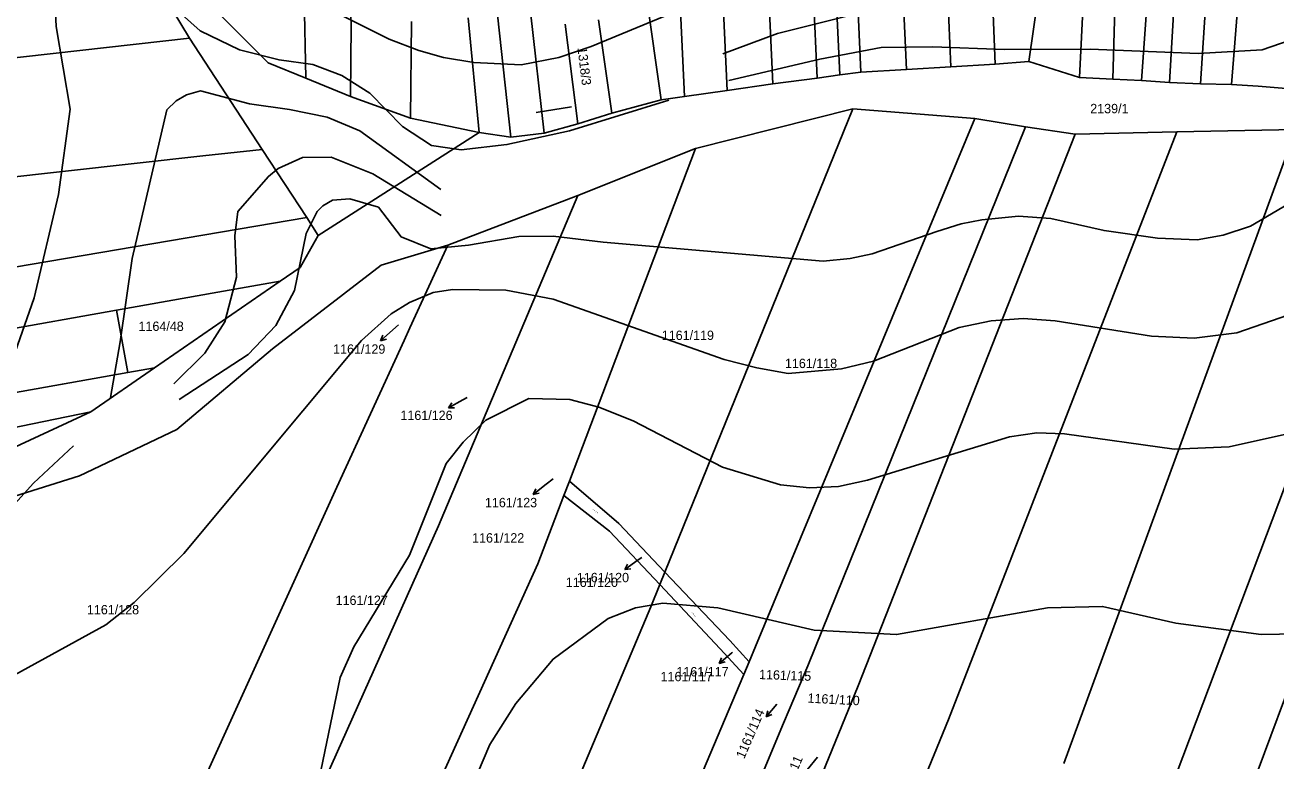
# Model space of a CAD drawing. Extents: x -555860 to -552701, y -1187050 to -1182291.
# Drawn here: x -554030 to -553802.7, y -1185298.6 to -1185165 of the extents above; entities that cross this region are included whole.
import ezdxf

# ---------------------------------------------------------------- set-up
doc = ezdxf.new("R2010")
doc.units = 0
for name, color, linetype in [('LEG_2b', 7, 'Continuous'), ('Level 16', 7, 'Continuous'), ('Level 40', 7, 'Continuous'), ('Level 41', 7, 'Continuous'), ('navrh_BV', 7, 'Continuous'), ('stav_BV', 7, 'Continuous')]:
    doc.layers.add(name, color=color, linetype=linetype)

msp = doc.modelspace()

# ---------------------------------------------------------------- linework, layer by layer
at = {"layer": 'Level 16'}
for p, q in [((-553963.18, -1185220.35), (-553965.44, -1185222.33)), ((-553965.44, -1185222.33), (-553965.01, -1185221.29)), ((-553965.44, -1185222.33), (-553964.35, -1185222.05)), ((-553950.47, -1185233.08), (-553953.09, -1185234.54)), ((-553953.09, -1185234.54), (-553952.46, -1185233.61)), ((-553953.09, -1185234.54), (-553951.98, -1185234.49)), ((-553935.32, -1185248.38), (-553937.67, -1185250.24)), ((-553937.67, -1185250.24), (-553937.2, -1185249.23)), ((-553937.67, -1185250.24), (-553936.58, -1185250.01)), ((-553918.61, -1185262.13), (-553921.05, -1185263.88)), ((-553921.05, -1185263.88), (-553920.53, -1185262.89)), ((-553921.05, -1185263.88), (-553919.94, -1185263.71)), ((-553901.61, -1185278.96), (-553903.88, -1185280.92)), ((-553903.88, -1185280.92), (-553903.45, -1185279.89)), ((-553903.88, -1185280.92), (-553902.8, -1185280.64)), ((-553893.43, -1185288.29), (-553895.33, -1185290.61)), ((-553895.33, -1185290.61), (-553895.08, -1185289.52)), ((-553895.33, -1185290.61), (-553894.31, -1185290.16)), ((-553886.01, -1185297.91), (-553887.92, -1185300.23))]:
    msp.add_line(p, q, dxfattribs=at)
for points in [[(-553962.18, -1185219.47), (-553963.18, -1185220.35)], [(-553949.67, -1185232.64), (-553950.47, -1185233.08)], [(-553934.07, -1185247.39), (-553935.32, -1185248.38)], [(-553917.96, -1185261.66), (-553918.61, -1185262.13)], [(-553901.49, -1185278.87), (-553901.61, -1185278.96)]]:
    msp.add_lwpolyline(points, dxfattribs=at)
at = {"layer": 'Level 40'}
for points in [[(-553913.02, -1185178.64), (-553931.08, -1185184.24), (-553942.46, -1185186.71), (-553950.78, -1185187.65), (-553956.18, -1185186.91), (-553961.4, -1185183.41), (-553967.38, -1185177.38), (-553972.48, -1185174.15), (-553977.75, -1185172.18), (-553983.86, -1185171.34), (-553991.03, -1185169.51), (-553998.2, -1185166.06), (-554011.29, -1185154.32), (-554013.93, -1185152.97), (-554017.65, -1185152.76), (-554020.58, -1185153.66), (-554021.78, -1185154.58), (-554022.94, -1185156.16), (-554024.6, -1185160.32), (-554024.33, -1185165.31), (-554021.83, -1185180.28), (-554023.91, -1185195.81), (-554028.34, -1185214.56), (-554033.07, -1185228.03)], [(-553902.14, -1185175.11), (-553885.58, -1185171.2), (-553874.47, -1185169.12), (-553865.1, -1185169), (-553852.06, -1185169.45), (-553836.49, -1185169.41), (-553816.87, -1185170.17), (-553805.26, -1185169.54), (-553798.36, -1185167.14), (-553789.85, -1185161.99), (-553780.44, -1185158.96), (-553772.79, -1185158.67), (-553764.12, -1185161.3), (-553755.24, -1185167.05), (-553745.59, -1185174.97), (-553739.62, -1185178.39), (-553727.19, -1185183.5), (-553721.46, -1185185.32)], [(-553796.24, -1185238.24), (-553811.21, -1185241.57), (-553821.2, -1185241.99), (-553841.16, -1185239.21), (-553846.15, -1185239.07), (-553851.15, -1185239.77), (-553876.94, -1185247.67), (-553882.2, -1185248.78), (-553887.47, -1185249.06), (-553892.74, -1185248.5), (-553903.28, -1185245.31), (-553919.5, -1185236.86), (-553925.74, -1185234.36), (-553931.01, -1185232.97), (-553938.5, -1185232.83), (-553946.27, -1185236.72), (-553950.42, -1185240.74), (-553953.47, -1185244.62), (-553960.13, -1185261.26), (-553970.25, -1185277.9), (-553972.75, -1185283.44), (-553977.68, -1185307.13)]]:
    msp.add_lwpolyline(points, dxfattribs=at)
at = {"layer": 'Level 41'}
for points in [[(-553801.78, -1185155.19), (-553806.02, -1185157.38), (-553811.77, -1185159.49), (-553818.42, -1185160.46), (-553831.73, -1185161.29), (-553863.35, -1185161.98), (-553874.79, -1185162.5), (-553879.99, -1185163.23), (-553893.3, -1185166.56), (-553903.21, -1185170.22)], [(-553973.43, -1185162.83), (-553963.86, -1185167.61), (-553958.47, -1185169.61), (-553953.96, -1185170.91), (-553948.48, -1185171.82), (-553939.89, -1185172.24), (-553933.04, -1185170.91), (-553927.13, -1185168.91), (-553903.84, -1185159.21)], [(-553954.49, -1185194.86), (-553969.2, -1185184.21), (-553975.1, -1185181.75), (-553981.94, -1185180.35), (-553989.25, -1185179.31), (-553998.12, -1185176.96), (-554000.66, -1185177.68), (-554002.56, -1185178.76), (-554004.22, -1185180.42), (-554010.55, -1185207.41), (-554012.73, -1185222.54), (-554014.47, -1185232.61)], [(-553930.71, -1185179.85), (-553937.14, -1185180.87)], [(-553954.43, -1185199.62), (-553966.81, -1185192.02), (-553974.42, -1185189), (-553979.57, -1185189.06), (-553983.99, -1185191.04), (-553985.78, -1185192.49), (-553991.33, -1185198.86), (-553991.88, -1185203.3), (-553991.6, -1185210.79), (-553993.71, -1185218.89), (-553997.33, -1185224.6), (-554002.96, -1185230.15)], [(-553797.35, -1185195.68), (-553807.33, -1185201.5), (-553812.32, -1185203.16), (-553817.04, -1185203.99), (-553824.25, -1185203.72), (-553833.95, -1185202.33), (-553843.66, -1185200.11), (-553849.48, -1185199.7), (-553856.14, -1185200.39), (-553859.94, -1185201.11), (-553864.32, -1185202.47), (-553876.11, -1185206.55), (-553880.07, -1185207.38), (-553884.98, -1185207.88), (-553924.96, -1185204.45), (-553934.08, -1185203.32), (-553940.28, -1185203.38), (-553949.43, -1185204.95), (-553956.31, -1185205.64), (-553961.69, -1185203.45), (-553965.81, -1185198.09), (-553971.02, -1185196.58), (-553974.13, -1185196.78), (-553975.9, -1185197.81), (-553976.91, -1185198.86), (-553978.96, -1185202.88), (-553981.07, -1185213.18)], [(-554035.01, -1185284.69), (-554015.32, -1185273.88), (-554010.19, -1185269.86), (-554001.17, -1185260.98), (-553968.86, -1185222.3), (-553963.46, -1185217.44), (-553960.13, -1185215.36), (-553955.83, -1185213.56), (-553952.37, -1185213.01), (-553942.66, -1185213.15), (-553934.06, -1185214.81), (-553903, -1185225.76), (-553897.03, -1185227.27), (-553891.36, -1185228.26), (-553881.65, -1185227.43), (-553875.83, -1185226.04), (-553860.3, -1185219.94), (-553854.47, -1185218.69), (-553848.65, -1185218.28), (-553842.83, -1185218.69), (-553825.36, -1185221.47), (-553817.59, -1185221.88), (-553809.83, -1185220.91), (-553794.3, -1185215.5)], [(-553981.07, -1185213.18), (-553984.44, -1185219.54), (-553989.49, -1185224.84), (-554002, -1185232.98)], [(-554021.22, -1185241.39), (-554028.47, -1185248.21), (-554034.75, -1185255.09), (-554054.83, -1185278.73), (-554058.01, -1185281.89), (-554061.35, -1185284), (-554064.11, -1185285.52), (-554077.7, -1185289.58), (-554081.16, -1185291.22), (-554083.38, -1185293.48), (-554084.58, -1185297.83), (-554085.41, -1185302.93), (-554089.23, -1185309.81)], [(-553957.22, -1185323.1), (-553945.57, -1185295.65), (-553940.86, -1185288.16), (-553934.06, -1185280.12), (-553924.08, -1185272.77), (-553919.09, -1185270.83), (-553914.1, -1185269.99), (-553904.11, -1185270.83), (-553886.64, -1185274.85), (-553871.67, -1185275.68), (-553844.21, -1185270.83), (-553834.23, -1185270.55), (-553820.92, -1185273.6), (-553805.39, -1185275.68), (-553792.08, -1185275.4)]]:
    msp.add_lwpolyline(points, dxfattribs=at)
at = {"layer": 'navrh_BV'}
for p, q in [((-553871.48, -1184943.44), (-553861.8, -1185172.59)), ((-553886.1, -1185174.65), (-553895.66, -1184961.33)), ((-553853.73, -1185172.13), (-553860.43, -1185014.18)), ((-553869.86, -1185173.07), (-553876.52, -1185022.52)), ((-553916.25, -1185048.91), (-553910.2, -1185177.97)), ((-553894.12, -1185175.66), (-553899.44, -1185059.48)), ((-553881.97, -1185174.05), (-553886.92, -1185063.5)), ((-553882.93, -1185062.95), (-553878.14, -1185173.59)), ((-553906.73, -1185082.71), (-553902.43, -1185176.91)), ((-553971.59, -1185142.12), (-553970.73, -1185165.02)), ((-553978.99, -1185174.65), (-553979.64, -1185144.82)), ((-553918.98, -1185146.31), (-553914.44, -1185178.6)), ((-554011.1, -1185149.21), (-554000.1, -1185167.42)), ((-553844.61, -1185150.85), (-553847.6, -1185171.64)), ((-553838.41, -1185174.56), (-553837.65, -1185158.7)), ((-553831.91, -1185158.95), (-553832.36, -1185174.84)), ((-553827.15, -1185175.08), (-553826.03, -1185159.03)), ((-553821.12, -1185159.16), (-553822.07, -1185175.42)), ((-553816.46, -1185175.68), (-553815.35, -1185159.4)), ((-553809.53, -1185159.58), (-553810.83, -1185175.84)), ((-553985.83, -1185171.9), (-553995.39, -1185162.33)), ((-553947.5, -1185184.53), (-553949.5, -1185163.72)), ((-553944.17, -1185163.18), (-553941.77, -1185185.36)), ((-553935.71, -1185184.62), (-553938.19, -1185162.64)), ((-553923.4, -1185181.02), (-553925.8, -1185164.09)), ((-553970.73, -1185165.02), (-553970.89, -1185177.98)), ((-553959.95, -1185181.92), (-553959.78, -1185164.38)), ((-553931.87, -1185164.86), (-553929.56, -1185182.94)), ((-554066.2, -1185174.75), (-554000.1, -1185167.42)), ((-554000.1, -1185167.42), (-553986.93, -1185187.59)), ((-553978.99, -1185174.65), (-553985.83, -1185171.9)), ((-553869.86, -1185173.07), (-553878.14, -1185173.59)), ((-553861.8, -1185172.59), (-553869.86, -1185173.07)), ((-553853.73, -1185172.13), (-553861.8, -1185172.59)), ((-553847.6, -1185171.64), (-553853.73, -1185172.13)), ((-553838.41, -1185174.56), (-553847.6, -1185171.64)), ((-553970.89, -1185177.98), (-553978.99, -1185174.65)), ((-553886.1, -1185174.65), (-553894.12, -1185175.66)), ((-553881.97, -1185174.05), (-553886.1, -1185174.65)), ((-553878.14, -1185173.59), (-553881.97, -1185174.05)), ((-553832.36, -1185174.84), (-553838.41, -1185174.56)), ((-553827.15, -1185175.08), (-553832.36, -1185174.84)), ((-553822.07, -1185175.42), (-553827.15, -1185175.08)), ((-553816.46, -1185175.68), (-553822.07, -1185175.42)), ((-553902.43, -1185176.91), (-553910.2, -1185177.97)), ((-553894.12, -1185175.66), (-553902.43, -1185176.91)), ((-553810.83, -1185175.84), (-553816.46, -1185175.68)), ((-553805.94, -1185176.14), (-553810.83, -1185175.84)), ((-553800.13, -1185176.62), (-553805.94, -1185176.14)), ((-553959.95, -1185181.92), (-553970.89, -1185177.98)), ((-553914.44, -1185178.6), (-553923.4, -1185181.02)), ((-553910.2, -1185177.97), (-553914.44, -1185178.6)), ((-553947.5, -1185184.53), (-553959.95, -1185181.92)), ((-553923.4, -1185181.02), (-553929.56, -1185182.94)), ((-553879.62, -1185180.24), (-553913.77, -1185264.32)), ((-553908.21, -1185187.44), (-553879.62, -1185180.24)), ((-553857.41, -1185182), (-553897.27, -1185277.81)), ((-553879.62, -1185180.24), (-553857.41, -1185182)), ((-553857.41, -1185182), (-553848.22, -1185183.48)), ((-553976.73, -1185203.21), (-553947.5, -1185184.53)), ((-553941.77, -1185185.36), (-553947.5, -1185184.53)), ((-553929.56, -1185182.94), (-553935.71, -1185184.62)), ((-553848.22, -1185183.48), (-553887.8, -1185281.33)), ((-553820.75, -1185184.42), (-553862.21, -1185291.1)), ((-553848.22, -1185183.48), (-553839.2, -1185184.82)), ((-553799.1, -1185183.99), (-553841.28, -1185299.07)), ((-553839.2, -1185184.82), (-553820.75, -1185184.42)), ((-553820.75, -1185184.42), (-553799.1, -1185183.99)), ((-553935.71, -1185184.62), (-553941.77, -1185185.36)), ((-553839.2, -1185184.82), (-553878.63, -1185285)), ((-553777.39, -1185185.86), (-553822.75, -1185306.08)), ((-553997.73, -1185188.79), (-554155.32, -1185206.34)), ((-553986.93, -1185187.59), (-553997.73, -1185188.79)), ((-553978.84, -1185199.98), (-553986.93, -1185187.59)), ((-553908.21, -1185187.44), (-553931.11, -1185247.8)), ((-553929.57, -1185195.95), (-553908.21, -1185187.44)), ((-553764.71, -1185189.27), (-553809.95, -1185310.96)), ((-553929.57, -1185195.95), (-553954.87, -1185255.94)), ((-553953.2, -1185204.97), (-553929.57, -1185195.95)), ((-553978.84, -1185199.98), (-554091.35, -1185219.03)), ((-553978.84, -1185199.98), (-553976.73, -1185203.21)), ((-553980.01, -1185209.02), (-553976.73, -1185203.21)), ((-553965.29, -1185208.64), (-553953.2, -1185204.97)), ((-553953.2, -1185204.97), (-553960.08, -1185219.98)), ((-553985.07, -1185223.8), (-553965.29, -1185208.64)), ((-553983.66, -1185211.53), (-553980.01, -1185209.02)), ((-554006.5, -1185227.26), (-553983.66, -1185211.53)), ((-553994.99, -1185213.54), (-553983.66, -1185211.53)), ((-554013.37, -1185216.8), (-553994.99, -1185213.54)), ((-554146.79, -1185240.46), (-554013.37, -1185216.8)), ((-554011.36, -1185228.12), (-554013.37, -1185216.8)), ((-553960.08, -1185219.98), (-553961.15, -1185222.31)), ((-553961.15, -1185222.31), (-553973.34, -1185248.9)), ((-554002.44, -1185238.44), (-553985.07, -1185223.8)), ((-554018.08, -1185235.23), (-554006.5, -1185227.26)), ((-554006.5, -1185227.26), (-554011.36, -1185228.12)), ((-554011.36, -1185228.12), (-554145.41, -1185251.89)), ((-554064.16, -1185244.68), (-554018.08, -1185235.23)), ((-554046.19, -1185248.33), (-554018.08, -1185235.23)), ((-554020.12, -1185246.87), (-554002.44, -1185238.44)), ((-554044.05, -1185254.33), (-554020.12, -1185246.87)), ((-553931.11, -1185247.8), (-553932.1, -1185250.42)), ((-553931.11, -1185247.8), (-553922.15, -1185255.48)), ((-554006.28, -1185321.33), (-553973.34, -1185248.9)), ((-553932.1, -1185250.42), (-553936.82, -1185262.86)), ((-553923.8, -1185256.93), (-553932.1, -1185250.42)), ((-553990.5, -1185335.45), (-553954.87, -1185255.94)), ((-553914.69, -1185266.6), (-553923.8, -1185256.93)), ((-553922.15, -1185255.48), (-553913.77, -1185264.32)), ((-553977.24, -1185352.01), (-553936.82, -1185262.86)), ((-553913.77, -1185264.32), (-553914.69, -1185266.6)), ((-553913.77, -1185264.32), (-553901.98, -1185276.75)), ((-553914.69, -1185266.6), (-553916.32, -1185270.61)), ((-553903.71, -1185278.26), (-553914.69, -1185266.6)), ((-553962.65, -1185380.38), (-553916.32, -1185270.61)), ((-553901.98, -1185276.75), (-553898.47, -1185280.64)), ((-553899.43, -1185282.92), (-553903.71, -1185278.26)), ((-553897.27, -1185277.81), (-553898.47, -1185280.64)), ((-553898.47, -1185280.64), (-553899.43, -1185282.92)), ((-553891.16, -1185289.32), (-553887.8, -1185281.33)), ((-553899.43, -1185282.92), (-553949.7, -1185401.53)), ((-553878.63, -1185285), (-553916.62, -1185377.26)), ((-553900.4, -1185384.09), (-553862.21, -1185291.1)), ((-553892.18, -1185291.73), (-553891.16, -1185289.32)), ((-553943.64, -1185413.84), (-553892.18, -1185291.73))]:
    msp.add_line(p, q, dxfattribs=at)
at = {"layer": 'stav_BV'}
for p, q in [((-553917.96, -1185261.66), (-553918.61, -1185262.13)), ((-553918.61, -1185262.13), (-553921.04, -1185263.89)), ((-553921.04, -1185263.89), (-553920.52, -1185262.9)), ((-553921.04, -1185263.89), (-553919.93, -1185263.71)), ((-553901.61, -1185278.96), (-553903.88, -1185280.93)), ((-553903.88, -1185280.93), (-553903.45, -1185279.89)), ((-553901.49, -1185278.87), (-553901.61, -1185278.96)), ((-553903.88, -1185280.93), (-553902.79, -1185280.65))]:
    msp.add_line(p, q, dxfattribs=at)

# ---------------------------------------------------------------- texts
at = {"layer": 'LEG_2b'}
for s, height, rotation, p in [('1318/3', 1.7, 277, (-553929.65, -1185169.15)), ('1161/120', 0.2, 321, (-553926.91, -1185252.98)), ('1161/117', 0.2, 312, (-553908.97, -1185271.7)), ('1161/115', 1.7, 358, (-553896.67, -1185283.75)), ('1161/110', 1.7, 357, (-553887.87, -1185288.03))]:
    msp.add_text(s, height=height, rotation=rotation, dxfattribs=at).set_placement(p)
for s, p in [('2139/1', (-553836.47, -1185181.03)), ('1164/48', (-554009.39, -1185220.55)), ('1161/119', (-553914.32, -1185222.19)), ('1161/118', (-553891.94, -1185227.29)), ('1161/122', (-553948.79, -1185258.97)), ('1161/120', (-553931.77, -1185267.03)), ('1161/127', (-553973.58, -1185270.3)), ('1161/128', (-554018.77, -1185272)), ('1161/117', (-553914.54, -1185284.14))]:
    msp.add_text(s, height=1.7, dxfattribs=at).set_placement(p)
at = {"layer": 'Level 16'}
for s, p in [('1161/129', (-553974.03, -1185224.69)), ('1161/126', (-553961.81, -1185236.72)), ('1161/123', (-553946.45, -1185252.56)), ('1161/120', (-553929.75, -1185266.17)), ('1161/117', (-553911.66, -1185283.27))]:
    msp.add_text(s, height=1.7, dxfattribs=at).set_placement(p)
for s, p in [('1161/114', (-553899.35, -1185298.35)), ('1161/111', (-553892.41, -1185306.83))]:
    msp.add_text(s, height=1.7, rotation=66.6, dxfattribs=at).set_placement(p)

doc.saveas('drawing.dxf')
